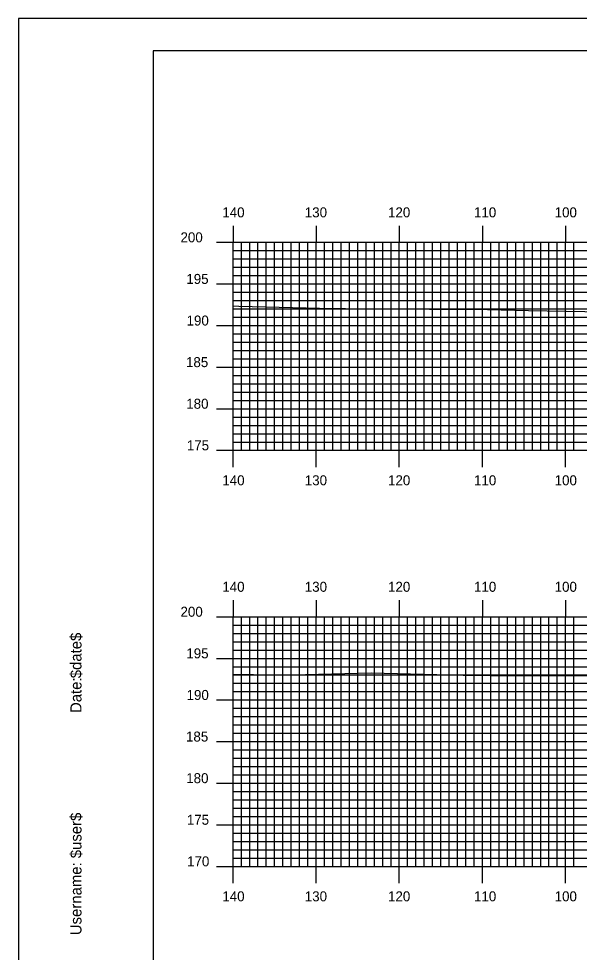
# Model space of a CAD drawing. Extents: x 1797207 to 1797550, y 442591 to 442811.
# Drawn here: x 1797207.1 to 1797274.6, y 442698.3 to 442810.5 of the extents above; entities that cross this region are included whole.
import ezdxf

# ---------------------------------------------------------------- set-up
doc = ezdxf.new("R2010")
doc.units = 0
for name, color, linetype in [('BORDER', 7, 'Continuous'), ('H_V ANNOTATION', 7, 'Continuous'), ('MAJOR', 7, 'Continuous'), ('MINOR', 7, 'Continuous'), ('PLOT BOUNDARY', 7, 'Continuous'), ('S_Roadway_Centerline', 7, 'Continuous')]:
    doc.layers.add(name, color=color, linetype=linetype)

msp = doc.modelspace()

# ---------------------------------------------------------------- linework, layer by layer
at = {"layer": 'BORDER'}
msp.add_lwpolyline([(1797223.33, 442596.67), (1797543.33, 442596.67), (1797543.33, 442806.67), (1797223.33, 442806.67)], close=True, dxfattribs=at)
at = {"layer": 'MAJOR'}
for p, q in [((1797232.93, 442785.67), (1797232.93, 442783.67)), ((1797242.93, 442785.67), (1797242.93, 442783.67)), ((1797252.93, 442785.67), (1797252.93, 442783.67)), ((1797262.93, 442785.67), (1797262.93, 442783.67)), ((1797272.93, 442785.67), (1797272.93, 442783.67)), ((1797230.93, 442783.67), (1797232.93, 442783.67)), ((1797232.93, 442783.67), (1797512.93, 442783.67)), ((1797232.93, 442758.67), (1797232.93, 442783.67)), ((1797232.93, 442758.67), (1797232.93, 442783.67)), ((1797232.93, 442783.67), (1797512.93, 442783.67)), ((1797242.93, 442758.67), (1797242.93, 442783.67)), ((1797252.93, 442758.67), (1797252.93, 442783.67)), ((1797262.93, 442758.67), (1797262.93, 442783.67)), ((1797272.93, 442758.67), (1797272.93, 442783.67)), ((1797230.93, 442778.67), (1797232.93, 442778.67)), ((1797232.93, 442778.67), (1797512.93, 442778.67)), ((1797230.93, 442773.67), (1797232.93, 442773.67)), ((1797232.93, 442773.67), (1797512.93, 442773.67)), ((1797230.93, 442768.67), (1797232.93, 442768.67)), ((1797232.93, 442768.67), (1797512.93, 442768.67)), ((1797230.93, 442763.67), (1797232.93, 442763.67)), ((1797232.93, 442763.67), (1797512.93, 442763.67)), ((1797230.93, 442758.67), (1797232.93, 442758.67)), ((1797232.93, 442758.67), (1797512.93, 442758.67)), ((1797232.93, 442758.67), (1797512.93, 442758.67)), ((1797232.93, 442756.66), (1797232.93, 442758.67)), ((1797242.93, 442756.66), (1797242.93, 442758.67)), ((1797252.93, 442756.66), (1797252.93, 442758.67)), ((1797262.93, 442756.66), (1797262.93, 442758.67)), ((1797272.93, 442756.66), (1797272.93, 442758.67)), ((1797232.93, 442740.67), (1797232.93, 442738.67)), ((1797242.93, 442740.67), (1797242.93, 442738.67)), ((1797252.93, 442740.67), (1797252.93, 442738.67)), ((1797262.93, 442740.67), (1797262.93, 442738.67)), ((1797272.93, 442740.67), (1797272.93, 442738.67)), ((1797230.93, 442738.67), (1797232.93, 442738.67)), ((1797232.93, 442738.67), (1797512.93, 442738.67)), ((1797232.93, 442708.67), (1797232.93, 442738.67)), ((1797232.93, 442708.67), (1797232.93, 442738.67)), ((1797232.93, 442738.67), (1797512.93, 442738.67)), ((1797242.93, 442708.67), (1797242.93, 442738.67)), ((1797252.93, 442708.67), (1797252.93, 442738.67)), ((1797262.93, 442708.67), (1797262.93, 442738.67)), ((1797272.93, 442708.67), (1797272.93, 442738.67)), ((1797230.93, 442733.67), (1797232.93, 442733.67)), ((1797232.93, 442733.67), (1797512.93, 442733.67)), ((1797230.93, 442728.67), (1797232.93, 442728.67)), ((1797232.93, 442728.67), (1797512.93, 442728.67)), ((1797230.93, 442723.67), (1797232.93, 442723.67)), ((1797232.93, 442723.67), (1797512.93, 442723.67)), ((1797230.93, 442718.67), (1797232.93, 442718.67)), ((1797232.93, 442718.67), (1797512.93, 442718.67)), ((1797230.93, 442713.67), (1797232.93, 442713.67)), ((1797232.93, 442713.67), (1797512.93, 442713.67)), ((1797230.93, 442708.67), (1797232.93, 442708.67)), ((1797232.93, 442708.67), (1797512.93, 442708.67)), ((1797232.93, 442708.67), (1797512.93, 442708.67)), ((1797232.93, 442706.66), (1797232.93, 442708.67)), ((1797242.93, 442706.66), (1797242.93, 442708.67)), ((1797252.93, 442706.66), (1797252.93, 442708.67)), ((1797262.93, 442706.66), (1797262.93, 442708.67)), ((1797272.93, 442706.66), (1797272.93, 442708.67))]:
    msp.add_line(p, q, dxfattribs=at)
at = {"layer": 'MINOR'}
for p, q in [((1797233.93, 442758.67), (1797233.93, 442783.67)), ((1797234.93, 442758.67), (1797234.93, 442783.67)), ((1797235.93, 442758.67), (1797235.93, 442783.67)), ((1797236.93, 442758.67), (1797236.93, 442783.67)), ((1797237.93, 442758.67), (1797237.93, 442783.67)), ((1797238.93, 442758.67), (1797238.93, 442783.67)), ((1797239.93, 442758.67), (1797239.93, 442783.67)), ((1797240.93, 442758.67), (1797240.93, 442783.67)), ((1797241.93, 442758.67), (1797241.93, 442783.67)), ((1797243.93, 442758.67), (1797243.93, 442783.67)), ((1797244.93, 442758.67), (1797244.93, 442783.67)), ((1797245.93, 442758.67), (1797245.93, 442783.67)), ((1797246.93, 442758.67), (1797246.93, 442783.67)), ((1797247.93, 442758.67), (1797247.93, 442783.67)), ((1797248.93, 442758.67), (1797248.93, 442783.67)), ((1797249.93, 442758.67), (1797249.93, 442783.67)), ((1797250.93, 442758.67), (1797250.93, 442783.67)), ((1797251.93, 442758.67), (1797251.93, 442783.67)), ((1797253.93, 442758.67), (1797253.93, 442783.67)), ((1797254.93, 442758.67), (1797254.93, 442783.67)), ((1797255.93, 442758.67), (1797255.93, 442783.67)), ((1797256.93, 442758.67), (1797256.93, 442783.67)), ((1797257.93, 442758.67), (1797257.93, 442783.67)), ((1797258.93, 442758.67), (1797258.93, 442783.67)), ((1797259.93, 442758.67), (1797259.93, 442783.67)), ((1797260.93, 442758.67), (1797260.93, 442783.67)), ((1797261.93, 442758.67), (1797261.93, 442783.67)), ((1797263.93, 442758.67), (1797263.93, 442783.67)), ((1797264.93, 442758.67), (1797264.93, 442783.67)), ((1797265.93, 442758.67), (1797265.93, 442783.67)), ((1797266.93, 442758.67), (1797266.93, 442783.67)), ((1797267.93, 442758.67), (1797267.93, 442783.67)), ((1797268.93, 442758.67), (1797268.93, 442783.67)), ((1797269.93, 442758.67), (1797269.93, 442783.67)), ((1797270.93, 442758.67), (1797270.93, 442783.67)), ((1797271.93, 442758.67), (1797271.93, 442783.67)), ((1797273.93, 442758.67), (1797273.93, 442783.67)), ((1797232.93, 442782.67), (1797512.93, 442782.67)), ((1797232.93, 442782.67), (1797234.94, 442782.67)), ((1797232.93, 442781.67), (1797512.93, 442781.67)), ((1797232.93, 442781.67), (1797234.94, 442781.67)), ((1797232.93, 442780.67), (1797512.93, 442780.67)), ((1797232.93, 442780.67), (1797234.94, 442780.67)), ((1797232.93, 442779.67), (1797512.93, 442779.67)), ((1797232.93, 442779.67), (1797234.94, 442779.67)), ((1797232.93, 442777.67), (1797512.93, 442777.67)), ((1797232.93, 442777.67), (1797234.94, 442777.67)), ((1797232.93, 442776.67), (1797512.93, 442776.67)), ((1797232.93, 442776.67), (1797234.94, 442776.67)), ((1797232.93, 442775.67), (1797512.93, 442775.67)), ((1797232.93, 442775.67), (1797234.94, 442775.67)), ((1797232.93, 442774.67), (1797512.93, 442774.67)), ((1797232.93, 442774.67), (1797234.94, 442774.67)), ((1797232.93, 442772.67), (1797512.93, 442772.67)), ((1797232.93, 442772.67), (1797234.94, 442772.67)), ((1797232.93, 442771.67), (1797512.93, 442771.67)), ((1797232.93, 442771.67), (1797234.94, 442771.67)), ((1797232.93, 442770.67), (1797512.93, 442770.67)), ((1797232.93, 442770.67), (1797234.94, 442770.67)), ((1797232.93, 442769.67), (1797512.93, 442769.67)), ((1797232.93, 442769.67), (1797234.94, 442769.67)), ((1797232.93, 442767.67), (1797512.93, 442767.67)), ((1797232.93, 442767.67), (1797234.94, 442767.67)), ((1797232.93, 442766.67), (1797512.93, 442766.67)), ((1797232.93, 442766.67), (1797234.94, 442766.67)), ((1797232.93, 442765.67), (1797512.93, 442765.67)), ((1797232.93, 442765.67), (1797234.94, 442765.67)), ((1797232.93, 442764.67), (1797512.93, 442764.67)), ((1797232.93, 442764.67), (1797234.94, 442764.67)), ((1797232.93, 442762.67), (1797512.93, 442762.67)), ((1797232.93, 442762.67), (1797234.94, 442762.67)), ((1797232.93, 442761.67), (1797512.93, 442761.67)), ((1797232.93, 442761.67), (1797234.94, 442761.67)), ((1797232.93, 442760.67), (1797512.93, 442760.67)), ((1797232.93, 442760.67), (1797234.94, 442760.67)), ((1797232.93, 442759.67), (1797512.93, 442759.67)), ((1797232.93, 442759.67), (1797234.94, 442759.67)), ((1797233.93, 442708.67), (1797233.93, 442738.67)), ((1797234.93, 442708.67), (1797234.93, 442738.67)), ((1797235.93, 442708.67), (1797235.93, 442738.67)), ((1797236.93, 442708.67), (1797236.93, 442738.67)), ((1797237.93, 442708.67), (1797237.93, 442738.67)), ((1797238.93, 442708.67), (1797238.93, 442738.67)), ((1797239.93, 442708.67), (1797239.93, 442738.67)), ((1797240.93, 442708.67), (1797240.93, 442738.67)), ((1797241.93, 442708.67), (1797241.93, 442738.67)), ((1797243.93, 442708.67), (1797243.93, 442738.67)), ((1797244.93, 442708.67), (1797244.93, 442738.67)), ((1797245.93, 442708.67), (1797245.93, 442738.67)), ((1797246.93, 442708.67), (1797246.93, 442738.67)), ((1797247.93, 442708.67), (1797247.93, 442738.67)), ((1797248.93, 442708.67), (1797248.93, 442738.67)), ((1797249.93, 442708.67), (1797249.93, 442738.67)), ((1797250.93, 442708.67), (1797250.93, 442738.67)), ((1797251.93, 442708.67), (1797251.93, 442738.67)), ((1797253.93, 442708.67), (1797253.93, 442738.67)), ((1797254.93, 442708.67), (1797254.93, 442738.67)), ((1797255.93, 442708.67), (1797255.93, 442738.67)), ((1797256.93, 442708.67), (1797256.93, 442738.67)), ((1797257.93, 442708.67), (1797257.93, 442738.67)), ((1797258.93, 442708.67), (1797258.93, 442738.67)), ((1797259.93, 442708.67), (1797259.93, 442738.67)), ((1797260.93, 442708.67), (1797260.93, 442738.67)), ((1797261.93, 442708.67), (1797261.93, 442738.67)), ((1797263.93, 442708.67), (1797263.93, 442738.67)), ((1797264.93, 442708.67), (1797264.93, 442738.67)), ((1797265.93, 442708.67), (1797265.93, 442738.67)), ((1797266.93, 442708.67), (1797266.93, 442738.67)), ((1797267.93, 442708.67), (1797267.93, 442738.67)), ((1797268.93, 442708.67), (1797268.93, 442738.67)), ((1797269.93, 442708.67), (1797269.93, 442738.67)), ((1797270.93, 442708.67), (1797270.93, 442738.67)), ((1797271.93, 442708.67), (1797271.93, 442738.67)), ((1797273.93, 442708.67), (1797273.93, 442738.67)), ((1797232.93, 442737.67), (1797512.93, 442737.67)), ((1797232.93, 442737.67), (1797234.94, 442737.67)), ((1797232.93, 442736.67), (1797512.93, 442736.67)), ((1797232.93, 442736.67), (1797234.94, 442736.67)), ((1797232.93, 442735.67), (1797512.93, 442735.67)), ((1797232.93, 442735.67), (1797234.94, 442735.67)), ((1797232.93, 442734.67), (1797512.93, 442734.67)), ((1797232.93, 442734.67), (1797234.94, 442734.67)), ((1797232.93, 442732.67), (1797512.93, 442732.67)), ((1797232.93, 442732.67), (1797234.94, 442732.67)), ((1797232.93, 442731.67), (1797512.93, 442731.67)), ((1797232.93, 442731.67), (1797234.94, 442731.67)), ((1797232.93, 442730.67), (1797512.93, 442730.67)), ((1797232.93, 442730.67), (1797234.94, 442730.67)), ((1797232.93, 442729.67), (1797512.93, 442729.67)), ((1797232.93, 442729.67), (1797234.94, 442729.67)), ((1797232.93, 442727.67), (1797512.93, 442727.67)), ((1797232.93, 442727.67), (1797234.94, 442727.67)), ((1797232.93, 442726.67), (1797512.93, 442726.67)), ((1797232.93, 442726.67), (1797234.94, 442726.67)), ((1797232.93, 442725.67), (1797512.93, 442725.67)), ((1797232.93, 442725.67), (1797234.94, 442725.67)), ((1797232.93, 442724.67), (1797512.93, 442724.67)), ((1797232.93, 442724.67), (1797234.94, 442724.67)), ((1797232.93, 442722.67), (1797512.93, 442722.67)), ((1797232.93, 442722.67), (1797234.94, 442722.67)), ((1797232.93, 442721.67), (1797512.93, 442721.67)), ((1797232.93, 442721.67), (1797234.94, 442721.67)), ((1797232.93, 442720.67), (1797512.93, 442720.67)), ((1797232.93, 442720.67), (1797234.94, 442720.67)), ((1797232.93, 442719.67), (1797512.93, 442719.67)), ((1797232.93, 442719.67), (1797234.94, 442719.67)), ((1797232.93, 442717.67), (1797512.93, 442717.67)), ((1797232.93, 442717.67), (1797234.94, 442717.67)), ((1797232.93, 442716.67), (1797512.93, 442716.67)), ((1797232.93, 442716.67), (1797234.94, 442716.67)), ((1797232.93, 442715.67), (1797512.93, 442715.67)), ((1797232.93, 442715.67), (1797234.94, 442715.67)), ((1797232.93, 442714.67), (1797512.93, 442714.67)), ((1797232.93, 442714.67), (1797234.94, 442714.67)), ((1797232.93, 442712.67), (1797512.93, 442712.67)), ((1797232.93, 442712.67), (1797234.94, 442712.67)), ((1797232.93, 442711.67), (1797512.93, 442711.67)), ((1797232.93, 442711.67), (1797234.94, 442711.67)), ((1797232.93, 442710.67), (1797512.93, 442710.67)), ((1797232.93, 442710.67), (1797234.94, 442710.67)), ((1797232.93, 442709.67), (1797512.93, 442709.67)), ((1797232.93, 442709.67), (1797234.94, 442709.67))]:
    msp.add_line(p, q, dxfattribs=at)
at = {"layer": 'PLOT BOUNDARY'}
msp.add_lwpolyline([(1797207.14, 442590.55), (1797547.14, 442590.55), (1797547.14, 442810.55), (1797207.14, 442810.55)], close=True, dxfattribs=at)
at = {"layer": 'S_Roadway_Centerline'}
for points in [[(1797232.93, 442776.04), (1797233.61, 442776.01), (1797243.32, 442775.74), (1797249.59, 442775.69), (1797263.52, 442775.6), (1797268.45, 442775.48), (1797275.26, 442775.35), (1797280.22, 442775.22), (1797283.93, 442775.19), (1797302.11, 442774.71), (1797303.06, 442774.67), (1797303.83, 442774.62), (1797315.6, 442774.15), (1797325.99, 442773.97), (1797330.16, 442773.85), (1797338.85, 442773.76), (1797346.65, 442773.7)], [(1797232.93, 442731.74), (1797235.39, 442731.72), (1797240.06, 442731.69), (1797249.55, 442731.92), (1797260.61, 442731.63), (1797264.02, 442731.59), (1797281.56, 442731.56), (1797285.28, 442731.4), (1797290.06, 442731.29), (1797306.55, 442730.77), (1797319.12, 442730.37), (1797322.28, 442730.3), (1797331.86, 442730.14), (1797343.1, 442729.66)]]:
    msp.add_lwpolyline(points, dxfattribs=at)

# ---------------------------------------------------------------- texts
at = {"layer": 'BORDER'}
for s, p in [('$date$', (1797214.7, 442731.28)), ('Date:', (1797214.7, 442727.1)), ('$user$', (1797214.7, 442709.65)), ('Username:', (1797214.7, 442700.4))]:
    msp.add_text(s, height=1.339, rotation=90, dxfattribs=at).set_placement(p)
at = {"layer": 'H_V ANNOTATION'}
for s, p in [('140', (1797231.64, 442786.67)), ('130', (1797241.56, 442786.67)), ('120', (1797251.57, 442786.67)), ('110', (1797261.91, 442786.67)), ('100', (1797271.61, 442786.67)), ('200', (1797226.61, 442783.67)), ('195', (1797227.31, 442778.67)), ('190', (1797227.34, 442773.67)), ('185', (1797227.27, 442768.67)), ('180', (1797227.3, 442763.67)), ('175', (1797227.37, 442758.67)), ('140', (1797231.64, 442754.47)), ('130', (1797241.56, 442754.47)), ('120', (1797251.57, 442754.47)), ('110', (1797261.91, 442754.47)), ('100', (1797271.61, 442754.47)), ('140', (1797231.64, 442741.67)), ('130', (1797241.56, 442741.67)), ('120', (1797251.57, 442741.67)), ('110', (1797261.91, 442741.67)), ('100', (1797271.61, 442741.67)), ('200', (1797226.61, 442738.67)), ('195', (1797227.31, 442733.67)), ('190', (1797227.34, 442728.67)), ('185', (1797227.27, 442723.67)), ('180', (1797227.3, 442718.67)), ('175', (1797227.37, 442713.67)), ('170', (1797227.4, 442708.67)), ('140', (1797231.64, 442704.47)), ('130', (1797241.56, 442704.47)), ('120', (1797251.57, 442704.47)), ('110', (1797261.91, 442704.47)), ('100', (1797271.61, 442704.47))]:
    msp.add_text(s, height=1.2, dxfattribs=at).set_placement(p)
at = {"layer": 'MAJOR'}
for p in [(1797232.92, 442758.67), (1797232.92, 442708.67)]:
    msp.add_text('-', height=0.012, dxfattribs=at).set_placement(p)

doc.saveas('drawing.dxf')
